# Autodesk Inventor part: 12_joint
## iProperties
Created: 2002-11
Part Number: 12_joint
Material: ABS (plastique)
Document SubType Name: Modélisation
Designer: FIEVET
Control State: 0
Master: False
Checked Out: False
Shininess: 21.0
Length Units: 11269
Angle Units: 11279
Time Units: 11290
Mass Units: 11283
Length Display Precision: 3
Angle Display Precision: 2
Compacted: True
Density: 1.06
Volumn: 0.30825488816936336
Area: 6.919040018065655
PropertySet Name: Model Information
Author: FIEVET
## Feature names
1. Révolution1 [Revolution]
